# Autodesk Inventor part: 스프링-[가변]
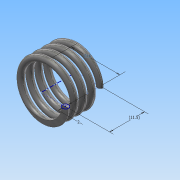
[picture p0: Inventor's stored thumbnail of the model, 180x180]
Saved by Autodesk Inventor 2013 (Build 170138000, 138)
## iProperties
Created: 2015-04
Part Number: 스프링-[가변]
Material: 강철, 탄소
Document SubType Name: Modeling
Designer: Administrator
Density: 7.87 g/cm^3
Mass: 4.78768 g
Surface Area: 12.5154 cm^2
Volume: 0.608346 cm^3
Author: Administrator
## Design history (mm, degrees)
sketch "스케치1"
  geometry: L1 (0, 0)-(8, 0); L2 (8, 0)-(8, 11.5); L3 (8, 11.5)-(0, 11.5); L4 (0, 11.5)-(0, 0); C1 r 1 at (8, 0)
  constraints: 8 end point, 2 parallel, 1 centre point, 1 coincident, 1 horizontal, 1 perpendicular
  dimensions: "d0" = 2 diameter of C1; "d1" = 16 diameter of L2 L4; "d2" = 11.50049 distance of L1.end L2.end (derived)
feature "코일1" pitch "d3" = 10; turns "d5" = 4; dims "d4" = 11.50049 (= d2), "d6" = 0, angle "d7" = 90 deg, angle "d8" = 90 deg, "d9" = 0, "d10" = 0
sketch "스케치2"
  geometry: L1 (-9, 0)-(-7, 0) reference; L2 (-9, 0)-(-7, 0) reference; 1 further point
  constraints: 2 horizontal alignment
extrude "돌출1" cut sketch "스케치2" stored distance "d11" = 10; taper "d12" = 0 deg
node "작업 평면1"
sketch "스케치3"
  geometry: L1 (9, 0)-(7, 0) reference; 1 further point
  constraints: 1 horizontal alignment
extrude "돌출2" cut sketch "스케치3" stored distance "d13" = 10; taper "d14" = 0 deg
node "솔리드1"
node "절단 모서리 투영1"
node "절단 모서리 투영2"
node "절단 모서리 투영3"
